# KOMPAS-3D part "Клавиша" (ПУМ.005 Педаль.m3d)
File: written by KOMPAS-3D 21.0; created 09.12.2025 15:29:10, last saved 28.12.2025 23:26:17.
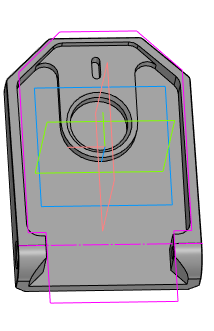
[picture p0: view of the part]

Document properties: Полное имя файла: C:\Users\Гузель\Desktop\ПУМ\ПУМ.005 Клавиша.m3d; Автор: User

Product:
- Part/product: Клавиша
    Материал: АМг6  ГОСТ 4784-2019 (density 2650 kg/m3)
    Масса: 0.114089
    Форматы листов документа: A4@4~2

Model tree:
1. Эскиз:1
2. Элемент выдавливания:1
     Расстояние 1 = 23
3. Эскиз:2  (with: Элемент выдавливания:1)
4. Скругление:2  (with: Элемент выдавливания:1)
     Радиус = 2
5. Элемент выдавливания:3
     Расстояние 1 = 36
6. Фаска:1  (with: Скругление:2, Элемент выдавливания:1)
     Угол = 45; Длина 1 = 4; Длина 2 = 4
7. Эскиз:3  (with: Элемент выдавливания:3, Скругление:3)
8. Элемент выдавливания:4
     Расстояние 2 = 18
9. Элемент выдавливания:5  (with: Элемент выдавливания:3, Элемент выдавливания:1)
     Толщина стенки 1 = 2.5; Расстояние 2 = 7.2
10. Зеркальный массив:1
11. Экземпляр ( 1 )
12. Экземпляр ( 2 )  (with: Элемент выдавливания:5)
13. Эскиз:4  (with: Элемент выдавливания:1, Фаска:1)
14. Элемент выдавливания:6
     Расстояние 2 = 2
15. Скругление:7  (with: Элемент выдавливания:6)
     Радиус = 6
16. Фаска:2  (with: Элемент выдавливания:6)
     Угол = 45; Длина 1 = 1; Длина 2 = 1
17. Эскиз:5  (with: Элемент выдавливания:4, Элемент выдавливания:3, Элемент выдавливания:5)
18. Элемент выдавливания:8
     Расстояние 1 = 4
19. Скругление:8  (with: Элемент выдавливания:8, Элемент выдавливания:4)
     Радиус = 5
20. Фаска:6  (with: Элемент выдавливания:8)
     Угол = 45; Длина 1 = 1.5; Длина 2 = 1.5
21. Фаска:7  (with: Элемент выдавливания:5)
     Угол = 45; Длина 1 = 0.5; Длина 2 = 0.5
22. Элемент выдавливания:10
     Расстояние 2 = 1
23. Элемент выдавливания:11
     Расстояние 2 = 1.5
24. Фаска:8  (with: Элемент выдавливания:4)
     Угол = 45; Длина 1 = 6; Длина 2 = 6
25. Скругление:11  (with: Элемент выдавливания:3)
     Радиус = 10
26. Фаска:9  (with: Элемент выдавливания:3)  (labels: АМг6  ГОСТ 4784-2019)
     Угол = 45; Длина 1 = 0.2; Длина 2 = 0.2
